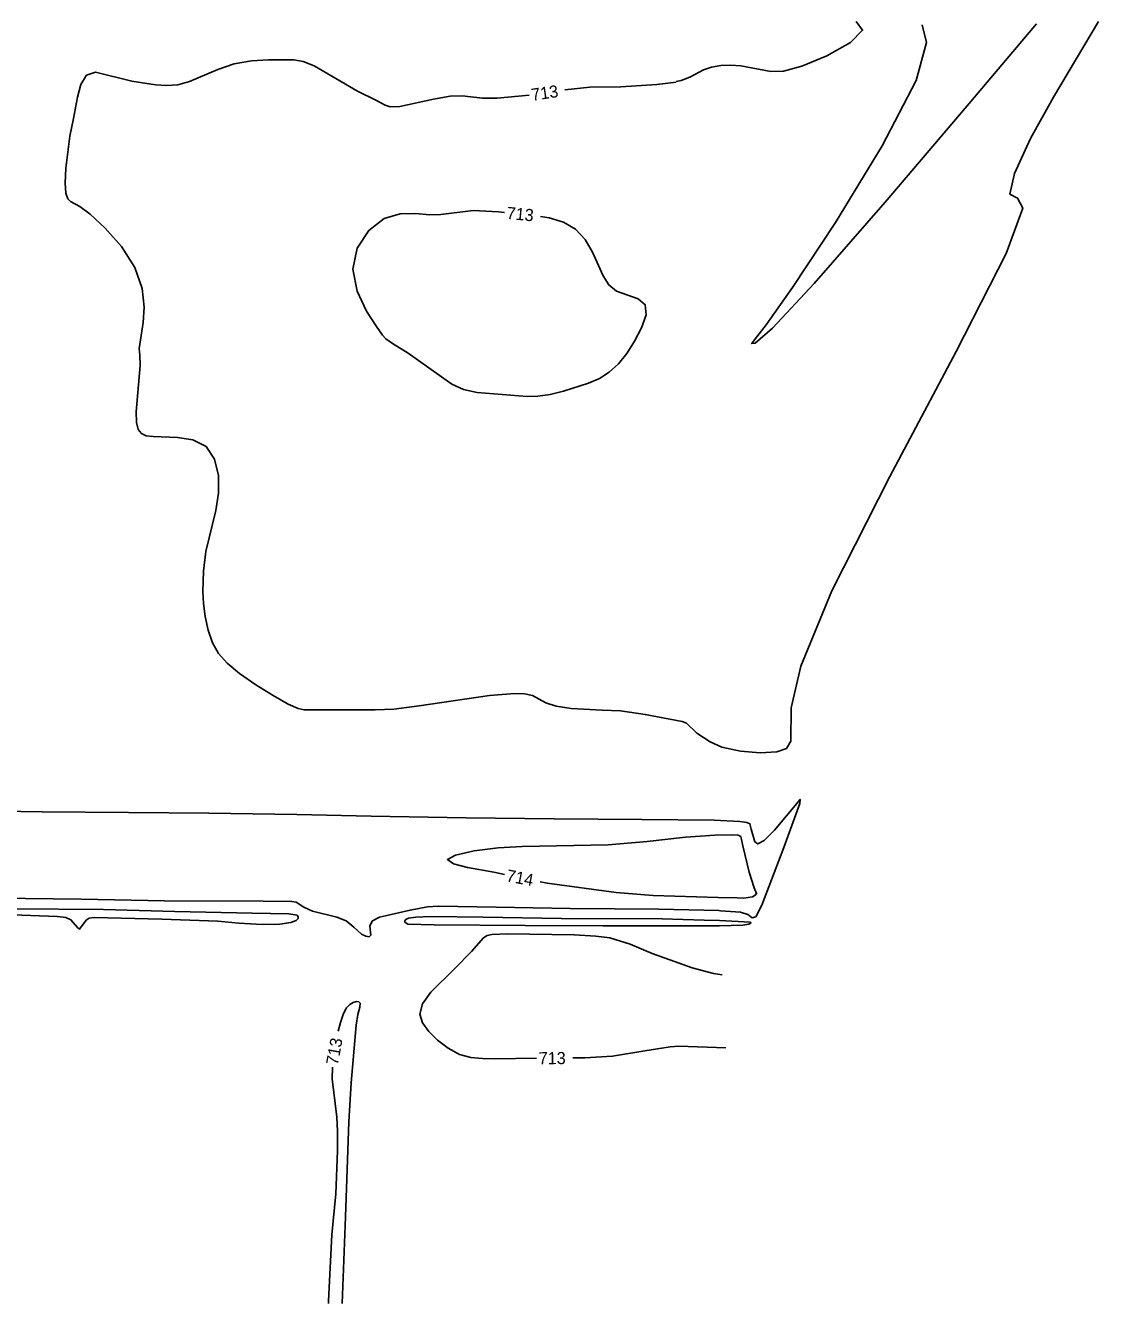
# Model space of a CAD drawing. Extents: x -468548933 to 3387700, y -306089263 to 1207014.
# Drawn here: x 1838881.6 to 1839236.2, y 536082.7 to 536505 of the extents above; entities that cross this region are included whole.
import ezdxf

# ---------------------------------------------------------------- set-up
doc = ezdxf.new("R2010")
doc.units = 0
doc.layers.add('DT_X_Contour_Minor', color=7, linetype='Continuous')
doc.layers.add('Level 19', color=7, linetype='Continuous')

msp = doc.modelspace()

# ---------------------------------------------------------------- linework, layer by layer
at = {"layer": 'DT_X_Contour_Minor'}
for points in [[(1839096.68, 536486.52), (1839098.31, 536486.88), (1839101.16, 536487.99), (1839105.69, 536490.39), (1839108.35, 536491.28), (1839111.39, 536491.82), (1839114.66, 536491.97), (1839118.04, 536491.7), (1839128, 536489.83), (1839132.15, 536489.97), (1839138.2, 536491.56), (1839146.47, 536495.01), (1839154.3, 536499.4), (1839158.31, 536503.49), (1839156.17, 536506.42)], [(1839107.9, 536268.31), (1839111.72, 536266.58), (1839117.95, 536265.21), (1839124.47, 536264.72), (1839129.9, 536265.03), (1839133.16, 536266.17), (1839134.55, 536268.53), (1839134.66, 536279.62), (1839137.86, 536293.33), (1839148.11, 536318.24), (1839167.28, 536356.05), (1839189.22, 536397.29), (1839205.78, 536429.7), (1839211.24, 536444.64), (1839209.51, 536448.02), (1839206.93, 536449.35), (1839208.48, 536456.13), (1839213.83, 536467.69), (1839221.34, 536481.34), (1839236.24, 536506.39)], [(1839215.73, 536505.57), (1839192.85, 536478.46), (1839165.75, 536446.64), (1839142.31, 536419.76), (1839128.53, 536405.06), (1839122.81, 536400.08), (1839121.67, 536399.94), (1839122.54, 536401.2), (1839126.39, 536406.12), (1839135.08, 536418.43), (1839149.28, 536439.99), (1839164.74, 536465.26), (1839176.01, 536486.87), (1839179.37, 536499.42), (1839178.03, 536505.27)], [(1839048.05, 536482.06), (1839037.49, 536481.05), (1839032.63, 536481.03), (1839025.92, 536481.86), (1839021.98, 536481.74), (1839016.48, 536480.73), (1839005.31, 536478.32), (1839002.18, 536478.17), (1839000.45, 536478.69), (1838997.43, 536480.36), (1838991.34, 536483.39), (1838977.01, 536491.77), (1838973.44, 536493.19), (1838970.31, 536493.71), (1838961.92, 536493.73), (1838956.37, 536493.35), (1838950.63, 536492.33), (1838945.23, 536490.49), (1838935.86, 536486.5), (1838931.92, 536485.49), (1838928.26, 536485.21), (1838924.62, 536485.42), (1838916.77, 536486.69), (1838904.77, 536489.58), (1838901.8, 536488.62), (1838899.9, 536485.55), (1838898.81, 536481.33), (1838897.54, 536474.36), (1838896.27, 536468.43), (1838894.98, 536457.89), (1838894.72, 536452.94), (1838894.94, 536449.64), (1838895.57, 536447.78), (1838896.48, 536446.86), (1838899.63, 536445.22), (1838902.96, 536442.71), (1838907.91, 536438.12), (1838913.35, 536431.97), (1838917.81, 536425.07), (1838920.18, 536418.17), (1838920.84, 536411.92), (1838920.56, 536406.92), (1838919.22, 536398.29), (1838919.44, 536396.07), (1838919.47, 536392.67), (1838918.15, 536377.43), (1838918.26, 536373.85), (1838918.87, 536371.56), (1838919.93, 536370.22), (1838921.47, 536369.5), (1838923.79, 536369.19), (1838931.91, 536368.95), (1838936.98, 536368.12), (1838941.34, 536365.88), (1838944.12, 536361.78), (1838945.38, 536356.37), (1838945.42, 536350.46), (1838944.57, 536344.77), (1838941.18, 536331.2), (1838940.43, 536324.77), (1838940.2, 536318.01), (1838940.42, 536314.09), (1838940.98, 536309.73), (1838941.95, 536305.26), (1838943.38, 536301.1), (1838945.38, 536297.54), (1838948.25, 536294.29), (1838952.33, 536290.92), (1838957.72, 536287.19), (1838963.48, 536283.6), (1838968.45, 536280.83), (1838971.73, 536279.36), (1838973.71, 536278.89), (1838997.15, 536278.95), (1839003.37, 536279.11), (1839011.77, 536280.21), (1839035.02, 536283.61), (1839043.36, 536284.31), (1839046.55, 536284.18), (1839049.14, 536283.6), (1839053.65, 536281.22), (1839057.05, 536280.08), (1839061.92, 536279.35), (1839072.19, 536278.85), (1839078.28, 536278.61), (1839086.43, 536277.39), (1839098.7, 536275.07), (1839100.1, 536274.46), (1839103.55, 536271.21), (1839107.9, 536268.31)], [(1839096.69, 536486.27), (1839090.24, 536485.52), (1839078.37, 536484.83), (1839068.19, 536484.64), (1839059.93, 536483.75)], [(1839002.87, 536400), (1839000.69, 536401.46), (1838999.67, 536402.68), (1838997.63, 536405.54), (1838994.37, 536410.61), (1838991.2, 536417.25), (1838989.77, 536424.5), (1838991.29, 536431.45), (1838995.13, 536437.29), (1839000.18, 536441.23), (1839005.49, 536442.83), (1839010.58, 536442.87), (1839015.13, 536442.48), (1839018.89, 536442.55), (1839029.59, 536443.89), (1839037.92, 536443.45), (1839039.93, 536443.25)], [(1839051.85, 536441.91), (1839054.66, 536441.47), (1839059.42, 536440.08), (1839063.43, 536437.76), (1839066.61, 536434.29), (1839069.07, 536430.13), (1839072.6, 536422.28), (1839074.4, 536419.35), (1839076.95, 536417.26), (1839084.09, 536414.74), (1839086.47, 536412.76), (1839086.71, 536409.43), (1839085.27, 536405.19), (1839082.92, 536400.74), (1839080.33, 536396.69), (1839077.56, 536393.22), (1839074.58, 536390.44), (1839071.33, 536388.38), (1839067.75, 536386.82), (1839059.47, 536384.23), (1839055.08, 536383.16), (1839051, 536382.52), (1839047.44, 536382.44), (1839030.88, 536383.8), (1839026.35, 536384.77), (1839022.55, 536386.53), (1839008.07, 536396.77), (1839002.87, 536400)], [(1839109.24, 536242.41), (1839117.69, 536242.06), (1839120.08, 536241.73), (1839121.04, 536241.25), (1839121.51, 536239.5), (1839122.62, 536235.26), (1839123.68, 536234.61), (1839125.78, 536235.73), (1839129.13, 536239.16), (1839137.64, 536249.33), (1839137.51, 536248), (1839132.27, 536233.45), (1839124.96, 536214.36), (1839122.99, 536210.54), (1839121.78, 536210.21), (1839120.35, 536211.29), (1839117.97, 536212.07), (1839111.37, 536212.53), (1839110.77, 536212.55)], [(1838858.67, 536245.59), (1838887.16, 536245.2), (1838915.69, 536244.96), (1838942.17, 536244.73), (1838971.29, 536244.27), (1838995.85, 536243.8), (1839027.23, 536243.22), (1839056.38, 536242.92), (1839085.35, 536242.71), (1839109.24, 536242.41)], [(1839039.93, 536224.47), (1839036.4, 536225.22), (1839027.73, 536226.78), (1839023.03, 536227.99), (1839021.07, 536229.42), (1839023.74, 536230.93), (1839029.94, 536232.31), (1839037.8, 536233.3), (1839045.75, 536233.75), (1839074.16, 536234.27), (1839087.04, 536235.44), (1839099.74, 536236.83), (1839109.49, 536237.48)], [(1839109.49, 536237.48), (1839114.99, 536237.64), (1839117.15, 536237.51), (1839118.05, 536237), (1839118.73, 536234.01), (1839120.77, 536225.28), (1839122.41, 536220.12), (1839123.24, 536218.22), (1839122.79, 536217.62), (1839121.9, 536217.08), (1839119.06, 536216.7), (1839116.84, 536216.73)], [(1839110.55, 536216.85), (1839089.06, 536217.52), (1839076.82, 536218.53), (1839054.08, 536221.65), (1839051.7, 536222.12)], [(1839110.77, 536212.55), (1839090.94, 536212.99), (1839061.6, 536213.29), (1839037.2, 536213.74), (1839018.11, 536214.07), (1839014.49, 536213.86), (1839008.71, 536212.72), (1838998.66, 536210.44), (1838996.27, 536209.23), (1838995.46, 536207.58), (1838995.77, 536204.5), (1838995.21, 536203.93), (1838994.07, 536204.08), (1838992.7, 536204.78), (1838990.14, 536207.1), (1838987.63, 536209.16), (1838984.54, 536210.36), (1838976.44, 536212.36), (1838973.58, 536213.68), (1838971.03, 536215.3), (1838969.62, 536215.53), (1838960.23, 536215.66), (1838927.52, 536215.81), (1838899.98, 536216.34), (1838872.28, 536216.69)], [(1839116.84, 536216.73), (1839110.55, 536216.85)], [(1838877.56, 536213.13), (1838907.39, 536212.97), (1838930.93, 536212.25), (1838956.49, 536211.76), (1838968.71, 536211.52), (1838971.4, 536211.09), (1838971.79, 536210.53), (1838971.78, 536209.92), (1838971.08, 536209.29), (1838969.29, 536208.63), (1838965.66, 536208.11), (1838959.81, 536208.02), (1838952.15, 536208.46), (1838945.19, 536209.02), (1838926.68, 536209.74), (1838904.29, 536210.26), (1838902.72, 536210.04), (1838901.63, 536209.37), (1838899.52, 536206.45), (1838898.79, 536207), (1838896.63, 536209.48), (1838894.93, 536210.26), (1838892.21, 536210.65), (1838874.47, 536211.23)], [(1839111.03, 536207.56), (1839095.88, 536207.56), (1839072.52, 536207.58), (1839046.82, 536207.69), (1839016.73, 536207.89), (1839007.98, 536208.13), (1839007.02, 536208.72), (1839006.98, 536209.16), (1839007.3, 536209.63), (1839008.23, 536210.07), (1839010.65, 536210.41), (1839015.58, 536210.59), (1839032.84, 536210.39), (1839058.83, 536209.91), (1839092.01, 536209.79), (1839105.97, 536209.44), (1839110.94, 536209.26)], [(1839110.94, 536209.26), (1839121.21, 536208.69), (1839121.32, 536208.41), (1839120.67, 536208.07), (1839118.66, 536207.79), (1839111.03, 536207.56)], [(1839050.47, 536163.76), (1839036.73, 536163.63), (1839032.68, 536163.64), (1839028.8, 536163.99), (1839025.01, 536165.05), (1839021.28, 536167.06), (1839017.83, 536169.71), (1839014.9, 536172.61), (1839012.81, 536175.43), (1839011.97, 536178.37), (1839012.85, 536181.7), (1839015.64, 536185.58), (1839023.52, 536193.47), (1839029.06, 536199.09), (1839032.99, 536203.6), (1839034.18, 536204.31), (1839035.76, 536204.68), (1839040.94, 536204.85), (1839062.98, 536204.51), (1839070.11, 536204.12), (1839074.7, 536203.51), (1839081.45, 536201.42), (1839088.7, 536198.36), (1839101.97, 536193.7), (1839108.98, 536191.76), (1839111.87, 536191.33)], [(1838984.98, 536172.7), (1838985.69, 536175.62), (1838986.71, 536178.56), (1838987.72, 536180.41), (1838988.78, 536181.52), (1838989.92, 536182.19), (1838990.99, 536182.48), (1838991.8, 536182.4), (1838992.21, 536181.97), (1838992.13, 536180.63), (1838991.44, 536178.2), (1838990.93, 536174.69), (1838989.24, 536155.61), (1838988.49, 536142.78), (1838987.37, 536111.33), (1838986.28, 536082.75)], [(1839113.11, 536167.21), (1839097.53, 536167.72), (1839094.64, 536167.55), (1839086.32, 536166.25), (1839075.64, 536164.46), (1839066.47, 536163.86), (1839062.47, 536163.86)], [(1838981.81, 536082.78), (1838981.72, 536083.62), (1838982.88, 536105.39), (1838984.18, 536118.97), (1838984.78, 536133.14), (1838984.79, 536139.72), (1838984.53, 536144.29), (1838983, 536157.02), (1838983.13, 536160.84)]]:
    msp.add_lwpolyline(points, dxfattribs=at)

# ---------------------------------------------------------------- texts
at = {"layer": 'Level 19'}
for s, rotation, p in [('713', 8.3938, (1839049.11, 536480.14)), ('713', 354.3171, (1839040.5, 536441.18)), ('714', 349.0172, (1839040.31, 536222.29)), ('713', 79.6411, (1838984.85, 536161.31)), ('713', 0.5329, (1839051.26, 536161.77))]:
    msp.add_text(s, height=4, rotation=rotation, dxfattribs=at).set_placement(p)

doc.saveas('drawing.dxf')
